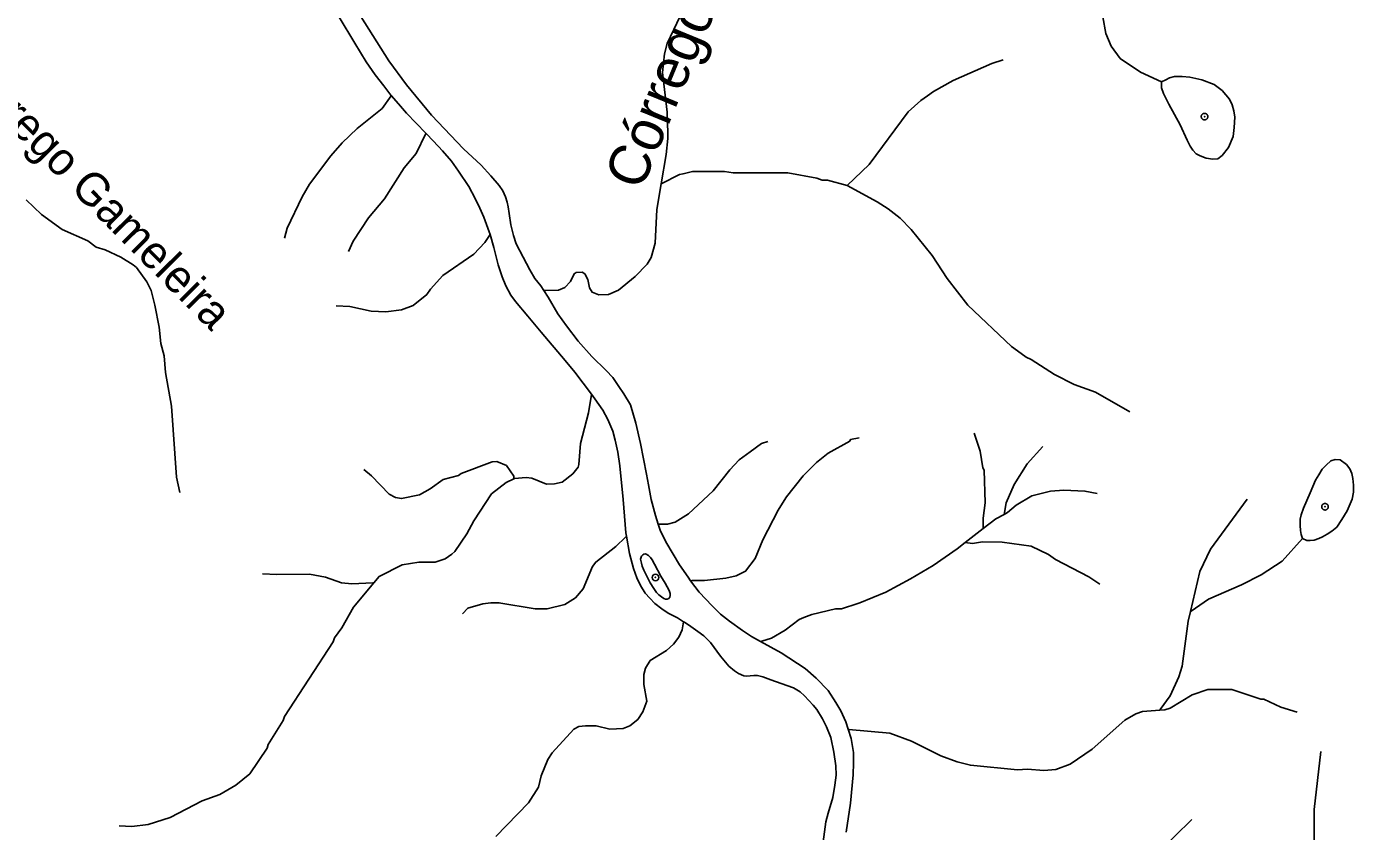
# Model space of a CAD drawing. Extents: x 393 to 446.6, y 8175.5 to 8231.
# Drawn here: x 413.59 to 420.07, y 8223.04 to 8226.97 of the extents above; entities that cross this region are included whole.
import ezdxf
from ezdxf.enums import TextEntityAlignment as Align

# ---------------------------------------------------------------- set-up
doc = ezdxf.new("R2010")
doc.units = 0
doc.header["$LTSCALE"] = 0.064
doc.header["$PDMODE"] = 32
doc.header["$PDSIZE"] = 0.032
doc.linetypes.add('LONG_DASHED', pattern=[7.5, 6, -1.5])
for name, color, linetype, lineweight in [('2', 7, 'Continuous', 25), ('3', 7, 'LONG_DASHED', 25), ('7', 7, 'Continuous', 25), ('9', 7, 'LONG_DASHED', 25)]:
    doc.layers.add(name, color=color, linetype=linetype, lineweight=lineweight)
doc.layers.add('54', color=7, linetype='Continuous')
doc.layers.add('61', color=7, linetype='Continuous')

msp = doc.modelspace()

# ---------------------------------------------------------------- linework, layer by layer
at = {"layer": '2'}
for points in [[(415.3735, 8226.6312), (415.3721, 8226.6327), (415.338, 8226.6783), (415.2956, 8226.732), (415.2517, 8226.7955), (415.1964, 8226.8867), (415.1199, 8227.0136)], [(416.1185, 8225.6786), (416.1034, 8225.7019), (416.0753, 8225.7383), (416.0505, 8225.7796), (416.0174, 8225.8424), (415.9844, 8225.9069), (415.9711, 8225.9482), (415.9579, 8225.9995), (415.9496, 8226.0557), (415.9447, 8226.0871), (415.9397, 8226.1103), (415.9314, 8226.1367), (415.9182, 8226.1665), (415.9, 8226.1913), (415.8604, 8226.2392), (415.8124, 8226.2905), (415.7264, 8226.3715), (415.571, 8226.5352), (415.4487, 8226.6839), (415.3611, 8226.8013), (415.2255, 8227.0179)], [(415.5429, 8226.4475), (415.4486, 8226.5449), (415.4096, 8226.5904), (415.3735, 8226.6312)], [(415.8563, 8225.9518), (415.8523, 8225.9654), (415.8262, 8226.037), (415.8067, 8226.081), (415.7839, 8226.1282), (415.753, 8226.1868), (415.7025, 8226.2617), (415.6684, 8226.3105), (415.6244, 8226.3609), (415.6049, 8226.3821), (415.5479, 8226.4423), (415.5429, 8226.4475)], [(416.3518, 8225.1719), (416.2706, 8225.2802), (416.2234, 8225.3372), (416.1062, 8225.4755), (416.0411, 8225.5536), (415.9809, 8225.6253), (415.9581, 8225.6562), (415.9337, 8225.7018), (415.9158, 8225.7457), (415.8962, 8225.8043), (415.8751, 8225.8889), (415.8563, 8225.9518)], [(416.6773, 8224.5381), (416.6638, 8224.5794), (416.6423, 8224.6587), (416.6291, 8224.7298), (416.6192, 8224.7811), (416.5911, 8224.9315), (416.568, 8225.0307), (416.5415, 8225.12), (416.5101, 8225.1745), (416.4853, 8225.2092), (416.4555, 8225.2539), (416.4225, 8225.2886), (416.353, 8225.3564), (416.2869, 8225.4308), (416.229, 8225.5068), (416.1877, 8225.5647), (416.1398, 8225.6457), (416.1185, 8225.6786)], [(416.5225, 8224.4793), (416.5196, 8224.4957), (416.5066, 8224.6585), (416.4903, 8224.8228), (416.4805, 8224.8896), (416.4675, 8224.9482), (416.4561, 8224.9921), (416.4317, 8225.0491), (416.4073, 8225.0947), (416.3682, 8225.15), (416.3518, 8225.1719)], [(416.8354, 8224.2613), (416.8226, 8224.2785), (416.7812, 8224.338), (416.7498, 8224.3909), (416.7151, 8224.4504), (416.687, 8224.5083), (416.6773, 8224.5381)], [(416.8012, 8224.0609), (416.7719, 8224.079), (416.7263, 8224.1034), (416.6954, 8224.123), (416.6612, 8224.1506), (416.6368, 8224.1751), (416.614, 8224.1995), (416.5912, 8224.2385), (416.5733, 8224.276), (416.557, 8224.3215), (416.5375, 8224.3948), (416.5225, 8224.4793)], [(417.1772, 8223.9644), (417.1334, 8223.9891), (417.0887, 8224.0172), (417.0259, 8224.0635), (416.9813, 8224.0983), (416.9399, 8224.1379), (416.8771, 8224.2057), (416.8354, 8224.2613)], [(417.4831, 8222.9853), (417.4962, 8223.0829), (417.5076, 8223.1253), (417.5303, 8223.2018), (417.5401, 8223.262), (417.5466, 8223.3108), (417.545, 8223.3564), (417.5352, 8223.4231), (417.5206, 8223.4947), (417.4994, 8223.5468), (417.4799, 8223.5859), (417.4522, 8223.6314), (417.4343, 8223.6526), (417.392, 8223.6982), (417.3708, 8223.7177), (417.3383, 8223.7372), (417.2781, 8223.7584), (417.2276, 8223.7763), (417.1885, 8223.7909), (417.1625, 8223.7975), (417.1446, 8223.7975), (417.1267, 8223.7958), (417.1088, 8223.7942), (417.0958, 8223.7958), (417.0697, 8223.8072), (417.0502, 8223.8202), (417.0225, 8223.843), (416.9818, 8223.8919), (416.933, 8223.9586), (416.9005, 8223.9911), (416.8712, 8224.0123), (416.837, 8224.0367), (416.8061, 8224.0579), (416.8012, 8224.0609)], [(417.6049, 8223.5352), (417.593, 8223.5725), (417.5682, 8223.6254), (417.545, 8223.6668), (417.507, 8223.7246), (417.4491, 8223.7858), (417.3946, 8223.8321), (417.2772, 8223.9081), (417.1772, 8223.9644)], [(417.5946, 8223.0319), (417.6161, 8223.1741), (417.6293, 8223.313), (417.631, 8223.3708), (417.631, 8223.4221), (417.6194, 8223.4899), (417.6049, 8223.5352)]]:
    msp.add_lwpolyline(points, dxfattribs=at)
msp.add_lwpolyline([(416.5906, 8224.3665), (416.5949, 8224.3463), (416.5996, 8224.3321), (416.6077, 8224.3121), (416.621, 8224.2841), (416.638, 8224.2501), (416.6558, 8224.2235), (416.6684, 8224.2042), (416.6802, 8224.1917), (416.6927, 8224.1821), (416.7053, 8224.1739), (416.712, 8224.1717), (416.7216, 8224.171), (416.729, 8224.1747), (416.7341, 8224.1806), (416.7349, 8224.1887), (416.7349, 8224.1983), (416.7304, 8224.2138), (416.7112, 8224.2486), (416.6905, 8224.2826), (416.6595, 8224.3417), (416.6469, 8224.3639), (416.6395, 8224.3742), (416.6299, 8224.3846), (416.6188, 8224.3912), (416.6144, 8224.392), (416.607, 8224.3912), (416.6018, 8224.3883), (416.5952, 8224.3809)], close=True, dxfattribs=at)
at = {"layer": '3'}
for points in [[(419.1351, 8226.6986), (419.1351, 8226.6683), (419.1449, 8226.6416), (419.1702, 8226.5897), (419.2263, 8226.4886), (419.26, 8226.4142), (419.2741, 8226.3833), (419.2867, 8226.365), (419.3036, 8226.3468), (419.3232, 8226.337), (419.3527, 8226.3257), (419.385, 8226.3201), (419.4088, 8226.3229), (419.4313, 8226.3384), (419.4622, 8226.3777), (419.4847, 8226.431), (419.4889, 8226.4745), (419.4917, 8226.5265), (419.4875, 8226.556), (419.479, 8226.5868), (419.4664, 8226.6135), (419.4313, 8226.6556), (419.392, 8226.6851), (419.3316, 8226.7076), (419.2727, 8226.7216), (419.2348, 8226.7244), (419.1983, 8226.7244), (419.173, 8226.7174), (419.1561, 8226.7076)], [(419.8234, 8224.4673), (419.8159, 8224.4872), (419.8134, 8224.5072), (419.8121, 8224.5309), (419.8109, 8224.5621), (419.8159, 8224.5833), (419.8284, 8224.6157), (419.8608, 8224.6906), (419.8858, 8224.7518), (419.902, 8224.7786), (419.9182, 8224.8054), (419.9382, 8224.8254), (419.9619, 8224.8466), (419.9831, 8224.8541), (420.0068, 8224.8516), (420.038, 8224.8291), (420.0542, 8224.8079), (420.063, 8224.7842), (420.0692, 8224.7605), (420.0717, 8224.728), (420.0717, 8224.7011), (420.0717, 8224.6944), (420.0654, 8224.6594), (420.0405, 8224.6033), (420.0143, 8224.5608), (419.9906, 8224.5234), (419.9669, 8224.5034), (419.9432, 8224.4885), (419.9207, 8224.4748), (419.902, 8224.4673), (419.8795, 8224.4598), (419.8596, 8224.4573), (419.8433, 8224.4573)]]:
    msp.add_lwpolyline(points, close=True, dxfattribs=at)
for p in [(419.3446, 8226.5285), (419.9328, 8224.6225)]:
    msp.add_point(p, dxfattribs=at)
at = {"layer": '54'}
msp.add_point((416.6637, 8224.2771), dxfattribs=at)
at = {"layer": '7'}
msp.add_line((418.2643, 8224.5158), (418.1761, 8224.4474), dxfattribs=at)
for points in [[(419.1351, 8226.6986), (419.0317, 8226.7456), (418.9332, 8226.8118), (418.8879, 8226.8732), (418.8621, 8226.9345), (418.8476, 8227.0153), (418.8588, 8227.1025), (418.9073, 8227.2317), (418.9832, 8227.3641), (419.022, 8227.448), (419.022, 8227.5385), (418.9687, 8227.6822), (418.8588, 8227.8388), (418.7684, 8227.9874), (418.7135, 8228.0363)], [(416.973, 8227.5062), (416.9375, 8227.3743), (416.9001, 8227.2349), (416.8, 8227.054), (416.7209, 8226.8861), (416.7079, 8226.8344), (416.6983, 8226.744), (416.7209, 8226.5502), (416.7234, 8226.4476), (416.7241, 8226.421), (416.716, 8226.3435), (416.6919, 8226.2007)], [(418.3608, 8226.8058), (418.3066, 8226.7875), (418.1177, 8226.7052), (418.0208, 8226.6519), (417.9921, 8226.6307), (417.9595, 8226.6067), (417.8981, 8226.5518), (417.7075, 8226.2951), (417.5994, 8226.1913)], [(414.852, 8225.9342), (414.8648, 8225.983), (414.9381, 8226.1368), (414.9753, 8226.1982), (415.0786, 8226.3371), (415.1335, 8226.4), (415.2078, 8226.4711), (415.3289, 8226.5679), (415.3728, 8226.6301), (415.3735, 8226.6312)], [(415.1645, 8225.8702), (415.1878, 8225.9202), (415.2627, 8226.0335), (415.3402, 8226.1271), (415.4371, 8226.2789), (415.4952, 8226.3484), (415.5423, 8226.4463), (415.5429, 8226.4475)], [(416.6919, 8226.2007), (416.6708, 8226.0755), (416.6627, 8225.9108), (416.6433, 8225.8397), (416.624, 8225.8074), (416.5643, 8225.7476), (416.4835, 8225.6814), (416.4351, 8225.6588), (416.3866, 8225.6572), (416.3543, 8225.6701), (416.3414, 8225.6927), (416.3333, 8225.7331), (416.3188, 8225.7606), (416.3059, 8225.7686), (416.2768, 8225.767), (416.2671, 8225.7606), (416.2493, 8225.7234), (416.2219, 8225.6943), (416.1896, 8225.6814), (416.1268, 8225.6789), (416.1185, 8225.6786)], [(417.5994, 8226.1913), (417.5041, 8226.2175), (417.4782, 8226.2175), (417.4524, 8226.2272), (417.3103, 8226.2531), (417.0438, 8226.2531), (417.0003, 8226.2611), (416.8452, 8226.2611), (416.7986, 8226.2495), (416.7807, 8226.245), (416.6919, 8226.2007)], [(418.98, 8225.086), (418.812, 8225.1824), (418.7087, 8225.2196), (418.6118, 8225.268), (418.4988, 8225.3423), (418.473, 8225.3536), (418.4674, 8225.3577), (418.4019, 8225.4053), (418.1888, 8225.6071), (418.0886, 8225.738), (418.0143, 8225.8494), (417.9126, 8225.9769), (417.8577, 8226.0318), (417.7996, 8226.0787), (417.7463, 8226.1126), (417.5994, 8226.1913)], [(415.1046, 8225.6035), (415.1723, 8225.6007), (415.2757, 8225.5781), (415.3467, 8225.5749), (415.4242, 8225.5846), (415.4807, 8225.6055), (415.5469, 8225.6589), (415.5647, 8225.6863), (415.626, 8225.7525), (415.7762, 8225.8558), (415.8311, 8225.914), (415.8538, 8225.948), (415.8563, 8225.9518)], [(415.9716, 8224.7589), (415.9756, 8224.7608), (416.033, 8224.7658), (416.0605, 8224.7626), (416.1315, 8224.7335), (416.1703, 8224.7351), (416.209, 8224.7432), (416.2607, 8224.7836), (416.2865, 8224.8159), (416.2897, 8224.8288), (416.2978, 8224.9322), (416.3365, 8225.0808), (416.3517, 8225.1714), (416.3518, 8225.1719)], [(418.2204, 8224.9827), (418.2485, 8224.8934), (418.2614, 8224.8127), (418.2679, 8224.8014), (418.2727, 8224.6415), (418.263, 8224.5672), (418.2643, 8224.5173), (418.2643, 8224.5158)], [(417.2129, 8224.9417), (417.1815, 8224.9312), (417.1264, 8224.8907), (417.0729, 8224.8514), (417.0261, 8224.803), (416.9453, 8224.6997), (416.8258, 8224.5882), (416.7596, 8224.5478), (416.7225, 8224.5382), (416.6799, 8224.5381), (416.6773, 8224.5381)], [(417.6588, 8224.9599), (417.6157, 8224.9506), (417.6123, 8224.9435), (417.5073, 8224.8837), (417.4492, 8224.8385), (417.3846, 8224.7739), (417.3038, 8224.6706), (417.2926, 8224.6528), (417.2634, 8224.606), (417.1875, 8224.4607), (417.1504, 8224.3702), (417.1036, 8224.3072), (417.0584, 8224.2846), (417.0067, 8224.2733), (416.9034, 8224.262), (416.8408, 8224.2614), (416.8354, 8224.2613)], [(418.555, 8224.9167), (418.4778, 8224.832), (418.4148, 8224.732), (418.376, 8224.6415), (418.3657, 8224.5854)], [(415.2399, 8224.805), (415.2773, 8224.7739), (415.3628, 8224.6835), (415.3952, 8224.6673), (415.4242, 8224.6625), (415.5114, 8224.6803), (415.5631, 8224.7093), (415.6277, 8224.7562), (415.7019, 8224.7755), (415.7149, 8224.7852), (415.8667, 8224.8417), (415.8893, 8224.8433), (415.9361, 8224.824), (415.9716, 8224.7723), (415.9716, 8224.759), (415.9716, 8224.7589)], [(415.2887, 8224.2508), (415.3145, 8224.282), (415.4275, 8224.3395), (415.5082, 8224.3524), (415.5889, 8224.3524), (415.6374, 8224.3686), (415.6697, 8224.3912), (415.6842, 8224.4041), (415.7423, 8224.4897), (415.7762, 8224.5543), (415.8634, 8224.6851), (415.9345, 8224.7416), (415.9716, 8224.7589)], [(418.8211, 8224.6874), (418.7605, 8224.6991), (418.657, 8224.7029), (418.5924, 8224.698), (418.502, 8224.6754), (418.4245, 8224.6302), (418.3825, 8224.5947), (418.3657, 8224.5854)], [(419.5527, 8224.6589), (419.374, 8224.4155), (419.3223, 8224.3057), (419.2755, 8224.1106)], [(418.3657, 8224.5854), (418.3249, 8224.5627), (418.2643, 8224.5158)], [(415.7222, 8224.0999), (415.7472, 8224.1264), (415.8215, 8224.149), (415.8602, 8224.1538), (415.899, 8224.1538), (416.0766, 8224.1232), (416.1347, 8224.1232), (416.2219, 8224.1457), (416.2736, 8224.178), (416.3107, 8224.2217), (416.3559, 8224.3299), (416.3721, 8224.3524), (416.4706, 8224.4283), (416.5175, 8224.4744), (416.5225, 8224.4793)], [(418.8339, 8224.2443), (418.7798, 8224.2798), (418.6167, 8224.3654), (418.5828, 8224.3896), (418.4988, 8224.4299), (418.3567, 8224.4493), (418.2598, 8224.451), (418.2114, 8224.4429), (418.1761, 8224.4474)], [(419.8234, 8224.4673), (419.7228, 8224.3573), (419.621, 8224.2895), (419.5258, 8224.241), (419.3643, 8224.1716), (419.2786, 8224.1127), (419.2755, 8224.1106)], [(418.1761, 8224.4474), (418.137, 8224.4171), (418.0192, 8224.3347), (417.9094, 8224.2701), (417.7883, 8224.2055), (417.6623, 8224.1538), (417.6519, 8224.1503), (417.5719, 8224.1231), (417.5428, 8224.1231), (417.4266, 8224.0957), (417.3878, 8224.0812), (417.3652, 8224.0715), (417.2974, 8224.0198), (417.2296, 8223.981), (417.1838, 8223.9665), (417.1772, 8223.9644)], [(414.7448, 8224.2953), (414.8147, 8224.2907), (414.9753, 8224.2927), (415.0528, 8224.2782), (415.1303, 8224.2507), (415.182, 8224.2459), (415.2842, 8224.2506), (415.2887, 8224.2508)], [(414.0455, 8223.063), (414.1066, 8223.0606), (414.1873, 8223.0703), (414.2939, 8223.1042), (414.4505, 8223.185), (414.5361, 8223.2173), (414.6152, 8223.2625), (414.683, 8223.3174), (414.7679, 8223.4423), (414.7686, 8223.4434), (414.7734, 8223.4611), (414.8461, 8223.579), (414.8526, 8223.5984), (415.0899, 8223.9633), (415.0964, 8223.9827), (415.1319, 8224.0311), (415.19, 8224.1313), (415.2887, 8224.2508)], [(419.2755, 8224.1106), (419.2642, 8224.0634), (419.2351, 8223.8438), (419.219, 8223.7921), (419.177, 8223.6985), (419.1285, 8223.6323), (419.1259, 8223.6288)], [(415.8849, 8223.0115), (416.0443, 8223.1753), (416.0927, 8223.2528), (416.1056, 8223.3077), (416.1379, 8223.3885), (416.1589, 8223.4207), (416.2655, 8223.5354), (416.2898, 8223.5483), (416.322, 8223.5515), (416.3737, 8223.5515), (416.4415, 8223.5354), (416.5061, 8223.5386), (416.5384, 8223.5515), (416.5772, 8223.5838), (416.6014, 8223.621), (416.6224, 8223.6727), (416.6062, 8223.7534), (416.6062, 8223.8034), (416.6143, 8223.8341), (416.6385, 8223.8712), (416.7177, 8223.9197), (416.7516, 8223.9504), (416.7774, 8223.9859), (416.7935, 8224.0214), (416.8012, 8224.0609)], [(419.7962, 8223.619), (419.7179, 8223.6436), (419.634, 8223.6823), (419.6195, 8223.6823), (419.4774, 8223.7292), (419.3611, 8223.7291), (419.2836, 8223.7033), (419.177, 8223.6387), (419.1512, 8223.6306), (419.1259, 8223.6288)], [(419.1259, 8223.6288), (419.0414, 8223.6226), (419.0091, 8223.6113), (418.9557, 8223.5806), (418.7959, 8223.4385), (418.6893, 8223.3642), (418.6183, 8223.3383), (418.5602, 8223.3335), (418.4794, 8223.34), (418.431, 8223.3367), (418.2017, 8223.3594), (418.1371, 8223.3755), (418.0563, 8223.4062), (417.9142, 8223.4772), (417.8077, 8223.516), (417.6072, 8223.535), (417.6049, 8223.5352)], [(419.9116, 8223.4268), (419.8794, 8223.143), (419.8794, 8222.9233), (419.8746, 8222.9008), (419.8584, 8222.8523), (419.7728, 8222.6876), (419.6275, 8222.3614), (419.6162, 8222.3033), (419.6291, 8222.2373)], [(419.2825, 8223.0939), (419.1172, 8222.9314), (419.0559, 8222.8539), (419.0446, 8222.8329), (419.0365, 8222.7942), (419.0365, 8222.7555), (419.0559, 8222.6925), (419.0704, 8222.6618), (419.1237, 8222.5988), (419.3514, 8222.3986), (419.5016, 8222.3), (419.5969, 8222.2467), (419.6291, 8222.2373)]]:
    msp.add_lwpolyline(points, dxfattribs=at)
at = {"layer": '9'}
msp.add_lwpolyline([(414.3418, 8224.6926), (414.3245, 8224.7675), (414.3003, 8225.1131), (414.2712, 8225.2778), (414.2648, 8225.3601), (414.2486, 8225.4199), (414.2405, 8225.5006), (414.2196, 8225.6072), (414.2018, 8225.6782), (414.1808, 8225.7218), (414.1291, 8225.7912), (414.113, 8225.8042), (414.0532, 8225.8413), (413.9774, 8225.8784), (413.9337, 8225.8913), (413.8918, 8225.922), (413.7674, 8225.9769), (413.6655, 8226.05), (413.5914, 8226.1223)], dxfattribs=at)

# ---------------------------------------------------------------- texts
at = {"layer": '61'}
for s, height, rotation, p in [('Córrego do Mutum', 0.2, 67.571, (417.0194, 8227.1918)), ('Córrego Gameleira', 0.16, 314.79, (413.8554, 8226.1223))]:
    msp.add_text(s, height=height, rotation=rotation, dxfattribs=at).set_placement(p, align=Align.CENTER)

doc.saveas('drawing.dxf')
